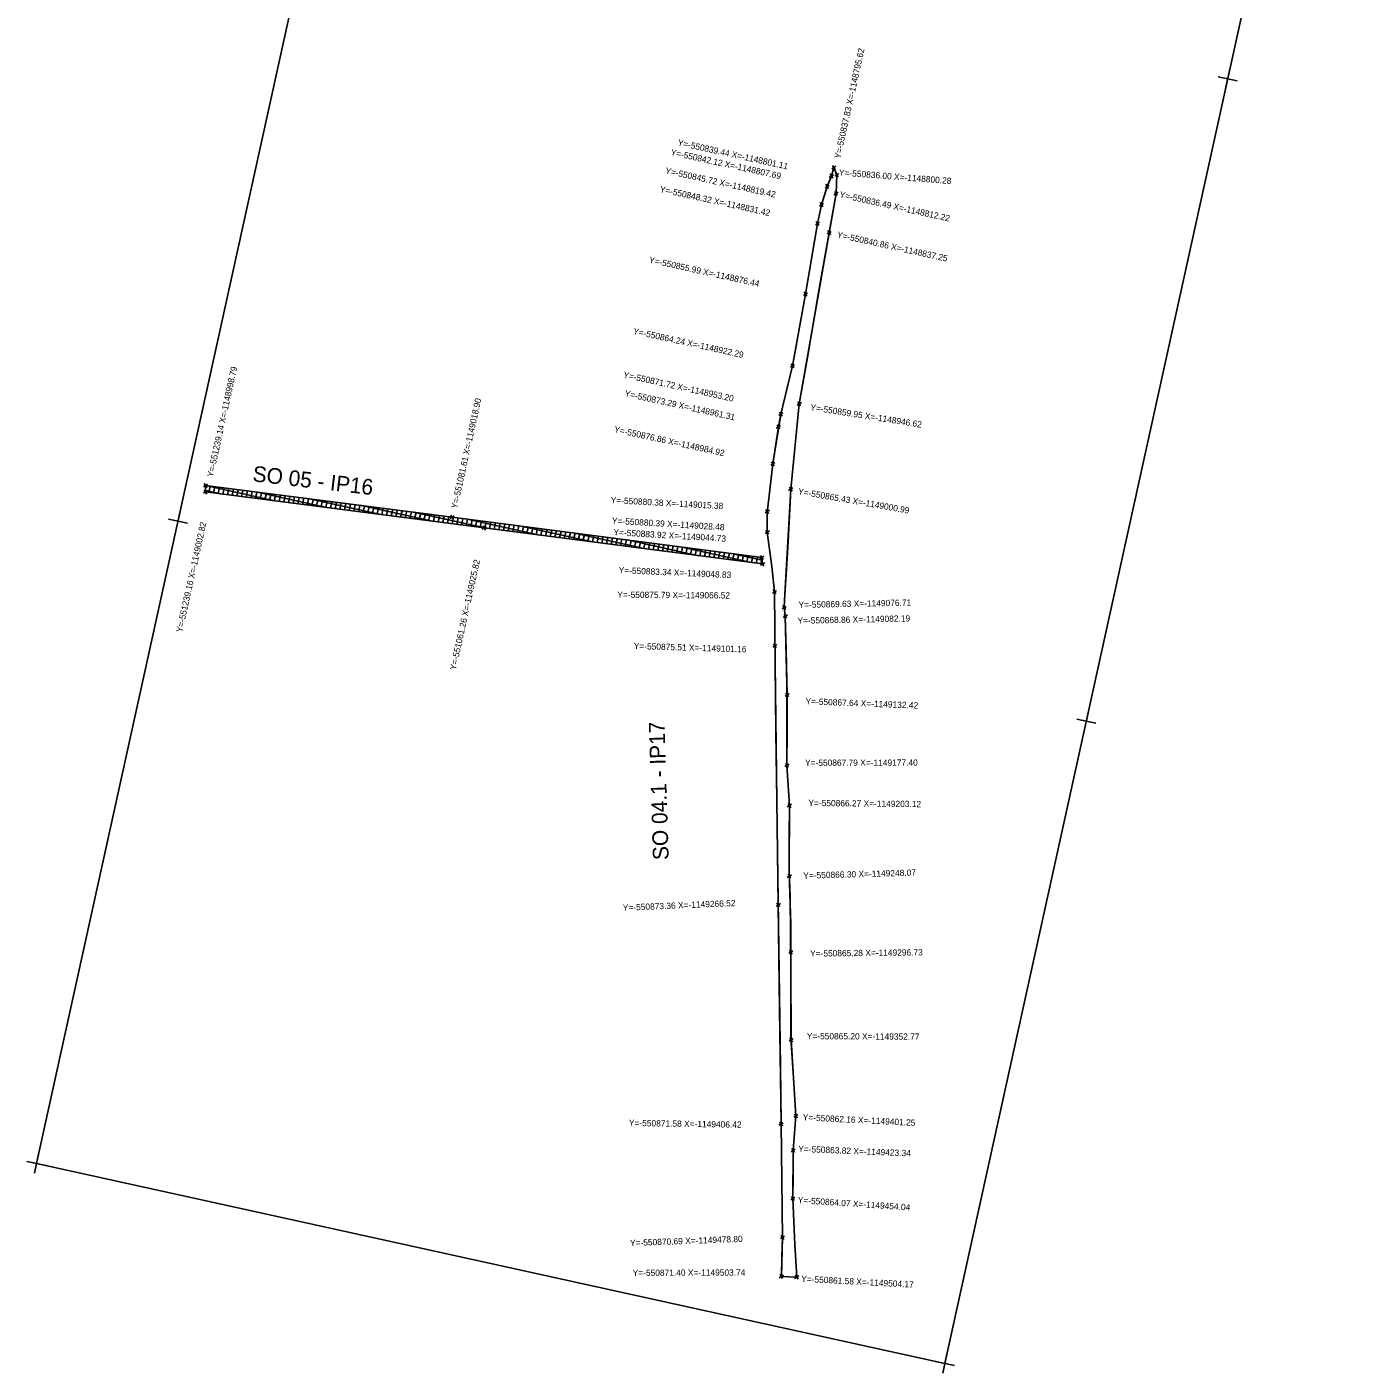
# Model space of a CAD drawing. Extents: x -551353 to -550490, y -1149565 to -1148201.
# Drawn here: x -551353 to -550496, y -1149565 to -1148706 of the extents above; entities that cross this region are included whole.
import ezdxf

# ---------------------------------------------------------------- set-up
doc = ezdxf.new("R2010")
doc.units = 0
for name, color, linetype in [('g_bod', 7, 'Continuous'), ('g_bod1', 7, 'Continuous'), ('u_IP16', 7, 'Continuous'), ('u_IP16_srafa', 7, 'Continuous'), ('u_IP17', 7, 'Continuous'), ('u_IP17_srafa', 7, 'Continuous'), ('u_popis', 7, 'Continuous'), ('u_souřadnice1', 7, 'Continuous'), ('u_souřadnice2', 7, 'Continuous'), ('x_formát_křížky', 7, 'Continuous'), ('x_formát_rám', 7, 'Continuous')]:
    doc.layers.add(name, color=color, linetype=linetype)

msp = doc.modelspace()

# ---------------------------------------------------------------- linework, layer by layer
at = {"layer": 'g_bod'}
for p, q in [((-551237.82, -1148997.95), (-551240.46, -1148999.63)), ((-551238.3, -1149000.11), (-551239.98, -1148997.47)), ((-551237.84, -1149001.98), (-551240.48, -1149003.66)), ((-551238.32, -1149004.14), (-551240, -1149001.5)), ((-551080.29, -1149018.06), (-551082.93, -1149019.74)), ((-551080.77, -1149020.22), (-551082.45, -1149017.58)), ((-551059.94, -1149024.98), (-551062.58, -1149026.66)), ((-551060.42, -1149027.14), (-551062.1, -1149024.5)), ((-550882.6, -1149043.89), (-550885.24, -1149045.57)), ((-550883.08, -1149046.05), (-550884.76, -1149043.41)), ((-550882.02, -1149047.99), (-550884.66, -1149049.67)), ((-550882.5, -1149050.15), (-550884.18, -1149047.51))]:
    msp.add_line(p, q, dxfattribs=at)
at = {"layer": 'g_bod1'}
for p, q in [((-550838.12, -1148800.27), (-550840.76, -1148801.95)), ((-550838.6, -1148802.43), (-550840.28, -1148799.79)), ((-550836.51, -1148794.78), (-550839.15, -1148796.46)), ((-550836.99, -1148796.94), (-550838.67, -1148794.3)), ((-550834.68, -1148799.44), (-550837.32, -1148801.12)), ((-550835.16, -1148801.6), (-550836.84, -1148798.96)), ((-550840.8, -1148806.85), (-550843.44, -1148808.53)), ((-550841.28, -1148809.01), (-550842.96, -1148806.37)), ((-550835.65, -1148813.54), (-550837.33, -1148810.9)), ((-550844.4, -1148818.58), (-550847.04, -1148820.26)), ((-550844.88, -1148820.74), (-550846.56, -1148818.1)), ((-550835.17, -1148811.38), (-550837.81, -1148813.06)), ((-550847, -1148830.58), (-550849.64, -1148832.26)), ((-550847.48, -1148832.74), (-550849.16, -1148830.1)), ((-550839.54, -1148836.41), (-550842.18, -1148838.09)), ((-550840.02, -1148838.57), (-550841.7, -1148835.93)), ((-550854.67, -1148875.6), (-550857.31, -1148877.28)), ((-550855.15, -1148877.76), (-550856.83, -1148875.12)), ((-550862.92, -1148921.45), (-550865.56, -1148923.13)), ((-550863.4, -1148923.61), (-550865.08, -1148920.97)), ((-550858.63, -1148945.78), (-550861.27, -1148947.46)), ((-550859.11, -1148947.94), (-550860.79, -1148945.3)), ((-550870.4, -1148952.36), (-550873.03, -1148954.04)), ((-550870.87, -1148954.52), (-550872.56, -1148951.89)), ((-550871.97, -1148960.47), (-550874.61, -1148962.15)), ((-550872.45, -1148962.63), (-550874.13, -1148959.99)), ((-550875.54, -1148984.08), (-550878.18, -1148985.76)), ((-550876.02, -1148986.24), (-550877.7, -1148983.6)), ((-550864.11, -1149000.15), (-550866.75, -1149001.83)), ((-550864.59, -1149002.31), (-550866.27, -1148999.67)), ((-550879.06, -1149014.54), (-550881.7, -1149016.23)), ((-550879.54, -1149016.7), (-550881.22, -1149014.07)), ((-550879.07, -1149027.64), (-550881.71, -1149029.32)), ((-550879.55, -1149029.8), (-550881.23, -1149027.16)), ((-550874.47, -1149065.68), (-550877.11, -1149067.36)), ((-550874.95, -1149067.84), (-550876.63, -1149065.2)), ((-550868.31, -1149075.87), (-550870.95, -1149077.55)), ((-550868.79, -1149078.03), (-550870.47, -1149075.39)), ((-550867.54, -1149081.35), (-550870.18, -1149083.03)), ((-550868.02, -1149083.51), (-550869.7, -1149080.87)), ((-550874.19, -1149100.31), (-550876.82, -1149102)), ((-550874.66, -1149102.47), (-550876.35, -1149099.84)), ((-550866.32, -1149131.58), (-550868.96, -1149133.26)), ((-550866.8, -1149133.74), (-550868.48, -1149131.1)), ((-550866.47, -1149176.56), (-550869.11, -1149178.24)), ((-550866.95, -1149178.72), (-550868.63, -1149176.08)), ((-550864.95, -1149202.28), (-550867.59, -1149203.96)), ((-550865.43, -1149204.44), (-550867.11, -1149201.8)), ((-550864.99, -1149247.23), (-550867.62, -1149248.92)), ((-550865.46, -1149249.39), (-550867.14, -1149246.76)), ((-550872.04, -1149265.68), (-550874.68, -1149267.36)), ((-550872.52, -1149267.84), (-550874.2, -1149265.2)), ((-550863.96, -1149295.89), (-550866.6, -1149297.57)), ((-550864.44, -1149298.05), (-550866.12, -1149295.41)), ((-550863.88, -1149351.93), (-550866.51, -1149353.61)), ((-550864.36, -1149354.09), (-550866.04, -1149351.45)), ((-550860.84, -1149400.41), (-550863.48, -1149402.09)), ((-550861.32, -1149402.57), (-550863, -1149399.93)), ((-550870.26, -1149405.58), (-550872.9, -1149407.27)), ((-550870.74, -1149407.74), (-550872.42, -1149405.11)), ((-550862.5, -1149422.5), (-550865.14, -1149424.18)), ((-550862.98, -1149424.66), (-550864.66, -1149422.02)), ((-550862.75, -1149453.2), (-550865.39, -1149454.88)), ((-550863.23, -1149455.36), (-550864.91, -1149452.72)), ((-550869.37, -1149477.96), (-550872.01, -1149479.64)), ((-550869.85, -1149480.12), (-550871.53, -1149477.48)), ((-550870.08, -1149502.9), (-550872.72, -1149504.58)), ((-550870.56, -1149505.06), (-550872.24, -1149502.42)), ((-550860.26, -1149503.33), (-550862.9, -1149505.01)), ((-550860.74, -1149505.49), (-550862.42, -1149502.85))]:
    msp.add_line(p, q, dxfattribs=at)
at = {"layer": 'u_IP16'}
msp.add_lwpolyline([(-551239.16, -1149002.82), (-551239.14, -1148998.79), (-551081.61, -1149018.9), (-550883.92, -1149044.73), (-550883.34, -1149048.83), (-551061.26, -1149025.82)], close=True, dxfattribs=at)
at = {"layer": 'u_IP16_srafa'}
for p, q in [((-551239.14, -1148998.79), (-551239.14, -1148998.79)), ((-551194.78, -1149008.56), (-551239.14, -1148998.79)), ((-551239.14, -1148998.79), (-551239.14, -1148998.79)), ((-551237.02, -1149003.1), (-551236.15, -1148999.17)), ((-551234.03, -1149003.48), (-551233.16, -1148999.55)), ((-551231.04, -1149003.87), (-551230.18, -1148999.93)), ((-551228.06, -1149004.26), (-551227.19, -1149000.32)), ((-551228.57, -1149004.19), (-551239.16, -1149001.86)), ((-551225.07, -1149004.64), (-551224.2, -1149000.7)), ((-551222.08, -1149005.03), (-551221.21, -1149001.08)), ((-551219.1, -1149005.41), (-551218.22, -1149001.46)), ((-551216.11, -1149005.8), (-551215.24, -1149001.84)), ((-551213.12, -1149006.19), (-551212.25, -1149002.22)), ((-551210.13, -1149006.57), (-551209.26, -1149002.6)), ((-551207.15, -1149006.96), (-551206.27, -1149002.99)), ((-551160.99, -1149012.93), (-551205.94, -1149003.03)), ((-551204.16, -1149007.34), (-551203.29, -1149003.37)), ((-551201.17, -1149007.73), (-551200.3, -1149003.75)), ((-551198.19, -1149008.12), (-551197.31, -1149004.13)), ((-551195.2, -1149008.5), (-551194.32, -1149004.51)), ((-551192.21, -1149008.89), (-551191.33, -1149004.89)), ((-551189.23, -1149009.28), (-551188.35, -1149005.27)), ((-551186.24, -1149009.66), (-551185.36, -1149005.66)), ((-551183.25, -1149010.05), (-551182.37, -1149006.04)), ((-551180.27, -1149010.43), (-551179.38, -1149006.42)), ((-551177.28, -1149010.82), (-551176.39, -1149006.8)), ((-551174.29, -1149011.21), (-551173.41, -1149007.18)), ((-551127.19, -1149017.3), (-551172.74, -1149007.27)), ((-551171.31, -1149011.59), (-551170.42, -1149007.56)), ((-551168.32, -1149011.98), (-551167.43, -1149007.94)), ((-551165.33, -1149012.36), (-551164.44, -1149008.33)), ((-551162.35, -1149012.75), (-551161.46, -1149008.71)), ((-551159.36, -1149013.14), (-551158.47, -1149009.09)), ((-551156.37, -1149013.52), (-551155.48, -1149009.47)), ((-551153.39, -1149013.91), (-551152.49, -1149009.85)), ((-551150.4, -1149014.3), (-551149.5, -1149010.23)), ((-551147.41, -1149014.68), (-551146.52, -1149010.61)), ((-551144.42, -1149015.07), (-551143.53, -1149011)), ((-551141.44, -1149015.45), (-551140.54, -1149011.38)), ((-551093.4, -1149021.66), (-551139.55, -1149011.5)), ((-551138.45, -1149015.84), (-551137.55, -1149011.76)), ((-551135.46, -1149016.23), (-551134.56, -1149012.14)), ((-551132.48, -1149016.61), (-551131.58, -1149012.52)), ((-551129.49, -1149017), (-551128.59, -1149012.9)), ((-551126.5, -1149017.38), (-551125.6, -1149013.28)), ((-551123.52, -1149017.77), (-551122.61, -1149013.67)), ((-551120.53, -1149018.16), (-551119.62, -1149014.05)), ((-551117.54, -1149018.54), (-551116.64, -1149014.43)), ((-551114.56, -1149018.93), (-551113.65, -1149014.81)), ((-551111.57, -1149019.32), (-551110.66, -1149015.19)), ((-551108.58, -1149019.7), (-551107.67, -1149015.57)), ((-551059.61, -1149026.03), (-551106.35, -1149015.74)), ((-551105.6, -1149020.09), (-551104.69, -1149015.95)), ((-551102.61, -1149020.47), (-551101.7, -1149016.34)), ((-551099.62, -1149020.86), (-551098.71, -1149016.72)), ((-551096.64, -1149021.25), (-551095.72, -1149017.1)), ((-551093.65, -1149021.63), (-551092.73, -1149017.48)), ((-551090.66, -1149022.02), (-551089.75, -1149017.86)), ((-551087.67, -1149022.4), (-551086.76, -1149018.24)), ((-551084.69, -1149022.79), (-551083.77, -1149018.62)), ((-551081.7, -1149023.18), (-551080.78, -1149019.01)), ((-551078.71, -1149023.56), (-551077.8, -1149019.4)), ((-551075.73, -1149023.95), (-551074.81, -1149019.79)), ((-551025.8, -1149030.41), (-551072.87, -1149020.04)), ((-551072.74, -1149024.34), (-551071.83, -1149020.18)), ((-551069.75, -1149024.72), (-551068.84, -1149020.57)), ((-551066.77, -1149025.11), (-551065.85, -1149020.96)), ((-551063.78, -1149025.49), (-551062.87, -1149021.35)), ((-551060.79, -1149025.88), (-551059.88, -1149021.74)), ((-551057.81, -1149026.27), (-551056.9, -1149022.13)), ((-551054.82, -1149026.65), (-551053.91, -1149022.52)), ((-551051.83, -1149027.04), (-551050.92, -1149022.91)), ((-551048.85, -1149027.43), (-551047.94, -1149023.3)), ((-551045.86, -1149027.81), (-551044.95, -1149023.69)), ((-551042.87, -1149028.2), (-551041.97, -1149024.08)), ((-551039.89, -1149028.58), (-551038.98, -1149024.47)), ((-550991.99, -1149034.78), (-551038.56, -1149024.53)), ((-551036.9, -1149028.97), (-551035.99, -1149024.86)), ((-551033.91, -1149029.36), (-551033.01, -1149025.25)), ((-551030.93, -1149029.74), (-551030.02, -1149025.64)), ((-551027.94, -1149030.13), (-551027.04, -1149026.03)), ((-551024.95, -1149030.52), (-551024.05, -1149026.42)), ((-551021.96, -1149030.9), (-551021.06, -1149026.81)), ((-551018.98, -1149031.29), (-551018.08, -1149027.2)), ((-551015.99, -1149031.67), (-551015.09, -1149027.59)), ((-551013, -1149032.06), (-551012.11, -1149027.98)), ((-551010.02, -1149032.45), (-551009.12, -1149028.37)), ((-551007.03, -1149032.83), (-551006.13, -1149028.76)), ((-550958.19, -1149039.15), (-551004.25, -1149029.01)), ((-551004.04, -1149033.22), (-551003.15, -1149029.15)), ((-551001.06, -1149033.61), (-551000.16, -1149029.54)), ((-550998.07, -1149033.99), (-550997.18, -1149029.93)), ((-550995.08, -1149034.38), (-550994.19, -1149030.32)), ((-550992.1, -1149034.76), (-550991.2, -1149030.71)), ((-550989.11, -1149035.15), (-550988.22, -1149031.1)), ((-550986.12, -1149035.54), (-550985.23, -1149031.49)), ((-550983.14, -1149035.92), (-550982.25, -1149031.88)), ((-550980.15, -1149036.31), (-550979.26, -1149032.27)), ((-550977.16, -1149036.7), (-550976.27, -1149032.66)), ((-550974.18, -1149037.08), (-550973.29, -1149033.05)), ((-550971.19, -1149037.47), (-550970.3, -1149033.44)), ((-550924.38, -1149043.52), (-550969.94, -1149033.49)), ((-550968.2, -1149037.85), (-550967.32, -1149033.83)), ((-550965.22, -1149038.24), (-550964.33, -1149034.22)), ((-550962.23, -1149038.63), (-550961.34, -1149034.61)), ((-550959.24, -1149039.01), (-550958.36, -1149035)), ((-550956.25, -1149039.4), (-550955.37, -1149035.39)), ((-550953.27, -1149039.79), (-550952.39, -1149035.78)), ((-550950.28, -1149040.17), (-550949.4, -1149036.17)), ((-550947.29, -1149040.56), (-550946.41, -1149036.56)), ((-550944.31, -1149040.95), (-550943.43, -1149036.95)), ((-550941.32, -1149041.33), (-550940.44, -1149037.34)), ((-550938.33, -1149041.72), (-550937.46, -1149037.73)), ((-550890.57, -1149047.89), (-550935.63, -1149037.97)), ((-550935.35, -1149042.1), (-550934.47, -1149038.13)), ((-550932.36, -1149042.49), (-550931.49, -1149038.52)), ((-550929.37, -1149042.88), (-550928.5, -1149038.91)), ((-550926.39, -1149043.26), (-550925.51, -1149039.3)), ((-550923.4, -1149043.65), (-550922.53, -1149039.69)), ((-550920.41, -1149044.04), (-550919.54, -1149040.08)), ((-550917.43, -1149044.42), (-550916.56, -1149040.47)), ((-550914.44, -1149044.81), (-550913.57, -1149040.86)), ((-550911.45, -1149045.19), (-550910.58, -1149041.25)), ((-550908.47, -1149045.58), (-550907.6, -1149041.64)), ((-550905.48, -1149045.97), (-550904.61, -1149042.03)), ((-550902.49, -1149046.35), (-550901.63, -1149042.42)), ((-550883.69, -1149046.34), (-550901.32, -1149042.46)), ((-550899.51, -1149046.74), (-550898.64, -1149042.81)), ((-550896.52, -1149047.13), (-550895.65, -1149043.2)), ((-550893.53, -1149047.51), (-550892.67, -1149043.59)), ((-550890.54, -1149047.9), (-550889.68, -1149043.98)), ((-550887.56, -1149048.28), (-550886.7, -1149044.37)), ((-550884.57, -1149048.67), (-550883.84, -1149045.33))]:
    msp.add_line(p, q, dxfattribs=at)
at = {"layer": 'u_IP17'}
for points in [[(-550837.83, -1148795.62), (-550839.44, -1148801.11), (-550842.12, -1148807.69), (-550845.72, -1148819.42), (-550848.32, -1148831.42), (-550855.99, -1148876.44), (-550864.24, -1148922.29), (-550871.72, -1148953.2), (-550873.29, -1148961.31), (-550876.86, -1148984.92), (-550879.01, -1149003.49), (-550880.48, -1149016.26), (-550880.39, -1149028.48), (-550877.44, -1149050.4), (-550875.79, -1149066.52), (-550875.6, -1149089.61), (-550875.41, -1149112.7), (-550874.83, -1149156.2), (-550874.24, -1149199.69), (-550873.8, -1149233.1), (-550872.03, -1149369.71), (-550871.14, -1149442.44), (-550870.69, -1149478.8), (-550871.4, -1149503.74), (-550861.58, -1149504.17)], [(-550837.83, -1148795.62), (-550836, -1148800.28), (-550836.49, -1148812.22), (-550840.86, -1148837.25), (-550847.41, -1148874.18), (-550854.67, -1148916.87), (-550859.95, -1148946.62), (-550865.43, -1149000.99), (-550867.06, -1149034.41), (-550867.87, -1149048.76), (-550869.33, -1149071.89)], [(-550869.33, -1149071.89), (-550869.63, -1149076.71), (-550868.86, -1149082.19), (-550868.38, -1149103.81), (-550867.64, -1149132.42), (-550867.72, -1149154.91), (-550867.79, -1149177.4), (-550866.27, -1149203.12), (-550866.43, -1149244.28), (-550866.14, -1149252.83), (-550865.28, -1149278.49), (-550865.28, -1149314.97), (-550865.28, -1149351.45), (-550863.68, -1149377.01), (-550862.16, -1149401.25), (-550863.82, -1149423.34), (-550863.95, -1149438.69), (-550864.07, -1149454.04), (-550862.79, -1149483.43), (-550861.58, -1149504.17)]]:
    msp.add_lwpolyline(points, dxfattribs=at)
at = {"layer": 'u_IP17_srafa'}
msp.add_lwpolyline([(-550871.4, -1149503.74), (-550861.58, -1149504.17), (-550862.79, -1149483.43), (-550864.07, -1149454.04), (-550863.82, -1149423.34), (-550862.16, -1149401.25), (-550865.2, -1149352.77), (-550865.28, -1149307.27), (-550865.85, -1149261.39), (-550866.43, -1149244.28), (-550866.35, -1149223.7), (-550866.27, -1149203.12), (-550867.79, -1149177.4), (-550867.89, -1149125.44), (-550868.86, -1149082.19), (-550869.63, -1149076.71), (-550869.33, -1149071.89), (-550865.43, -1149000.99), (-550859.95, -1148946.62), (-550844.14, -1148855.72), (-550836.49, -1148812.22), (-550836, -1148800.28), (-550837.83, -1148795.62), (-550839.44, -1148801.11), (-550842.12, -1148807.69), (-550845.72, -1148819.42), (-550848.32, -1148831.42), (-550852.16, -1148853.93), (-550855.99, -1148876.44), (-550863.13, -1148916.53), (-550864.24, -1148922.29), (-550867.72, -1148936.4), (-550871.19, -1148950.5), (-550872.24, -1148955.91), (-550876.86, -1148984.92), (-550880.48, -1149016.26), (-550880.39, -1149028.48), (-550877.44, -1149050.4), (-550875.79, -1149066.52), (-550875.41, -1149112.7), (-550874.24, -1149199.69), (-550873.36, -1149266.52), (-550872.48, -1149333.35), (-550871.59, -1149406.07), (-550870.69, -1149478.8), (-550871.05, -1149491.27)], close=True, dxfattribs=at)
at = {"layer": 'x_formát_křížky'}
for p, q in [((-550587.71, -1148745.13), (-550585.02, -1148732.92)), ((-550580.26, -1148740.37), (-550592.47, -1148737.68)), ((-551258.13, -1149027.57), (-551255.44, -1149015.37)), ((-551250.68, -1149022.81), (-551262.89, -1149020.12)), ((-550678.02, -1149155.31), (-550675.34, -1149143.1)), ((-550670.58, -1149150.55), (-550682.78, -1149147.86)), ((-551348.45, -1149437.75), (-551345.76, -1149425.54)), ((-551341, -1149432.99), (-551353.2, -1149430.3)), ((-550760.89, -1149560.72), (-550773.1, -1149558.03)), ((-550768.34, -1149565.48), (-550765.65, -1149553.27))]:
    msp.add_line(p, q, dxfattribs=at)
at = {"layer": 'x_formát_rám'}
msp.add_lwpolyline([(-550767, -1149559.38), (-550496.05, -1148328.85), (-551076.15, -1148201.12), (-551347.1, -1149431.64)], close=True, dxfattribs=at)

# ---------------------------------------------------------------- texts
at = {"layer": 'u_popis'}
for s, rotation, p in [('SO 05 - IP16', 353.38327, (-551209.45, -1148995.97)), ('SO 04.1 - IP17', 91.7421, (-550943.36, -1149237.73))]:
    msp.add_text(s, height=10, rotation=rotation, dxfattribs=at).set_placement(p)
at = {"layer": 'u_souřadnice1'}
for s, rotation, p in [('Y=-550837.83 X=-1148795.62', 77.58217, (-550833.71, -1148790.25)), ('Y=-550842.12 X=-1148807.69', 347.58217, (-550942.36, -1148787.67)), ('Y=-550839.44 X=-1148801.11', 347.58217, (-550937.86, -1148781.49)), ('Y=-550845.72 X=-1148819.42', 347.58217, (-550945.76, -1148799.44)), ('Y=-550836.00 X=-1148800.28', 355.58457, (-550834.71, -1148800.71)), ('Y=-550848.32 X=-1148831.42', 347.58217, (-550949.29, -1148811.24)), ('Y=-550836.49 X=-1148812.22', 347.58217, (-550834.52, -1148814.7)), ('Y=-550840.86 X=-1148837.25', 347.58217, (-550836.08, -1148840.35)), ('Y=-550855.99 X=-1148876.44', 347.58217, (-550956.18, -1148856.43)), ('Y=-550864.24 X=-1148922.29', 347.58217, (-550966.3, -1148901.87)), ('Y=-550871.72 X=-1148953.20', 347.58217, (-550972.59, -1148929.76)), ('Y=-550873.29 X=-1148961.31', 347.58217, (-550971.74, -1148941.68)), ('Y=-550859.95 X=-1148946.62', 350.96029, (-550853.12, -1148950.55)), ('Y=-550876.86 X=-1148984.92', 347.58217, (-550978.42, -1148964.61)), ('Y=-550880.38 X=-1149015.38', 356.89671, (-550980.46, -1149009.95)), ('Y=-550865.43 X=-1149000.99', 350.0552, (-550860.92, -1149004.27)), ('Y=-550880.39 X=-1149028.48', 356.57461, (-550979.68, -1149023.08)), ('Y=-550875.79 X=-1149066.52', 359.61937, (-550976.16, -1149070.41)), ('Y=-550869.63 X=-1149076.71', 1.20916, (-550860.4, -1149076.93)), ('Y=-550868.86 X=-1149082.19', 1.22699, (-550861.06, -1149087.05)), ('Y=-550875.51 X=-1149101.16', 358.25504, (-550965.69, -1149103.12)), ('Y=-550867.64 X=-1149132.42', 357.81419, (-550856.03, -1149138.44)), ('Y=-550867.79 X=-1149177.40', 0.05933, (-550856.26, -1149177.73)), ('Y=-550866.27 X=-1149203.12', 359.3826, (-550854.13, -1149203.37)), ('Y=-550866.30 X=-1149248.07', 1.56902, (-550857.33, -1149249.8)), ('Y=-550873.36 X=-1149266.52', 2.41246, (-550972.54, -1149270.32)), ('Y=-550865.28 X=-1149296.73', 0.63065, (-550853.02, -1149299.57)), ('Y=-550865.20 X=-1149352.77', 359.70926, (-550855.14, -1149352.28)), ('Y=-550871.58 X=-1149406.42', 359.06758, (-550968.78, -1149407.7)), ('Y=-550862.16 X=-1149401.25', 357.16833, (-550857.79, -1149404.09)), ('Y=-550863.82 X=-1149423.34', 357.66277, (-550860.7, -1149424.22)), ('Y=-550864.07 X=-1149454.04', 356.20261, (-550861.02, -1149456.94)), ('Y=-550870.69 X=-1149478.80', 2.16511, (-550967.97, -1149484.43)), ('Y=-550871.40 X=-1149503.74', 0.15231, (-550966.34, -1149503.43)), ('Y=-550861.58 X=-1149504.17', 356.98549, (-550858.83, -1149507.19))]:
    msp.add_text(s, height=4, rotation=rotation, dxfattribs=at).set_placement(p)
at = {"layer": 'u_souřadnice2'}
for s, rotation, p in [('Y=-551239.14 X=-1148998.79', 77.58217, (-551234.31, -1148993.54)), ('Y=-551081.61 X=-1149018.90', 77.58217, (-551078.42, -1149013.73)), ('Y=-551239.16 X=-1149002.82', 77.58217, (-551254, -1149092.78)), ('Y=-550883.92 X=-1149044.73', 356.66414, (-550978.7, -1149030.45)), ('Y=-551061.26 X=-1149025.82', 77.58217, (-551079.24, -1149116.78)), ('Y=-550883.34 X=-1149048.83', 357.4781, (-550975.37, -1149054.68))]:
    msp.add_text(s, height=4, rotation=rotation, dxfattribs=at).set_placement(p)

doc.saveas('drawing.dxf')
